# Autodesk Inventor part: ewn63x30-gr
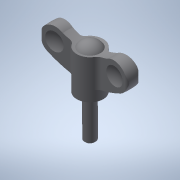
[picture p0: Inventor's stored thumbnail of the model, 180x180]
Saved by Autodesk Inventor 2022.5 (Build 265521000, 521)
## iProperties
Created: 2017-05
Part Number: ewn63x30-gr
Material: 一般
Document SubType Name: Modeling
Designer: imaocorp
Density: 1 g/cm^3
Appearance: 既定
Author: imaocorp
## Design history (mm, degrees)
node "ewn63x30-gr.x_t1"
node "ewn63x30-gr"
node "Base1"
